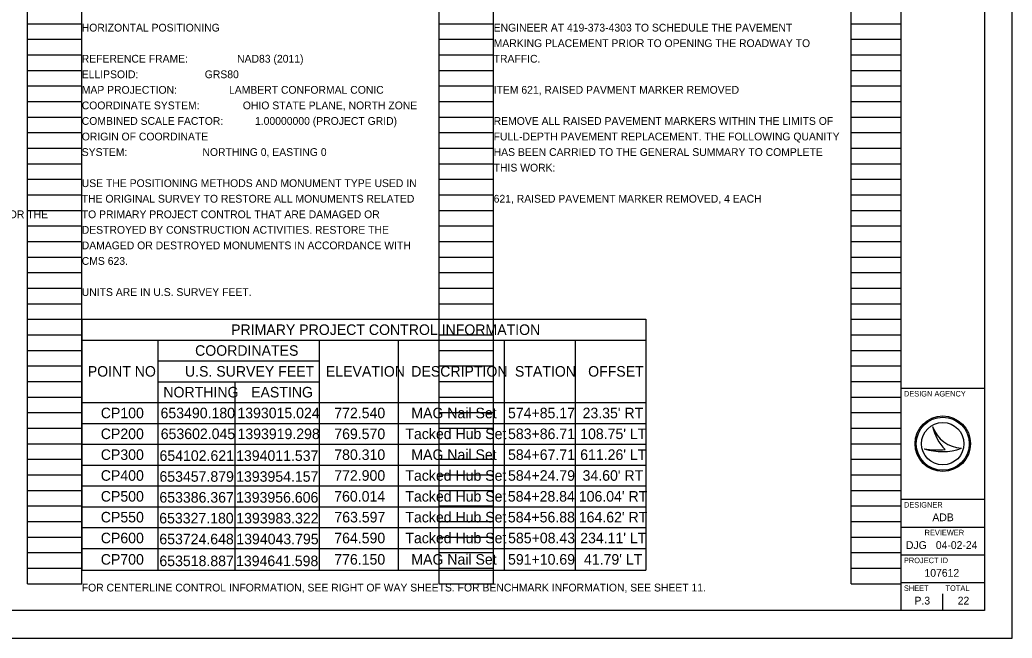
# Model space of a CAD drawing. Extents: x 0 to 34, y 0 to 22.
# Drawn here: x 16.13 to 34, y 0 to 11.13 of the extents above; entities that cross this region are included whole.
import ezdxf

# ---------------------------------------------------------------- set-up
doc = ezdxf.new("R2010")
doc.units = 0
for name, color, linetype in [('SH_Border', 7, 'Continuous'), ('SH_Cut_Line', 7, 'Continuous'), ('SH_Data', 7, 'Continuous'), ('SH_Text', 7, 'Continuous')]:
    doc.layers.add(name, color=color, linetype=linetype)

msp = doc.modelspace()

# ---------------------------------------------------------------- linework, layer by layer
at = {"layer": 'SH_Border'}
for p, q in [((32, 0.5), (32, 21.5)), ((32, 4.5), (33.5, 4.5)), ((32, 2.5), (33.5, 2.5)), ((32, 2), (33.5, 2)), ((32, 1.5), (33.5, 1.5)), ((32, 1), (33.5, 1))]:
    msp.add_line(p, q, dxfattribs=at)
msp.add_lwpolyline([(1.5, 21.5), (33.5, 21.5), (33.5, 0.5), (1.5, 0.5)], close=True, dxfattribs=at)
at = {"layer": 'SH_Cut_Line'}
msp.add_lwpolyline([(0, 0), (34, 0), (34, 22), (0, 22)], close=True, dxfattribs=at)
at = {"layer": 'SH_Data'}
for p, q in [((16.26, 0.98), (16.26, 21.14)), ((17.24, 0.98), (17.24, 21.14)), ((23.68, 0.98), (23.68, 21.14)), ((24.66, 0.98), (24.66, 21.14)), ((31.1, 0.98), (31.1, 21.14)), ((32, 0.98), (32, 21.14)), ((16.26, 11.06), (17.24, 11.06)), ((23.68, 11.06), (24.66, 11.06)), ((31.1, 11.06), (32, 11.06)), ((16.26, 10.78), (17.24, 10.78)), ((23.68, 10.78), (24.66, 10.78)), ((31.1, 10.78), (32, 10.78)), ((16.26, 10.5), (17.24, 10.5)), ((23.68, 10.5), (24.66, 10.5)), ((31.1, 10.5), (32, 10.5)), ((16.26, 10.22), (17.24, 10.22)), ((23.68, 10.22), (24.66, 10.22)), ((31.1, 10.22), (32, 10.22)), ((16.26, 9.94), (17.24, 9.94)), ((23.68, 9.94), (24.66, 9.94)), ((31.1, 9.94), (32, 9.94)), ((16.26, 9.66), (17.24, 9.66)), ((23.68, 9.66), (24.66, 9.66)), ((31.1, 9.66), (32, 9.66)), ((16.26, 9.38), (17.24, 9.38)), ((23.68, 9.38), (24.66, 9.38)), ((31.1, 9.38), (32, 9.38)), ((16.26, 9.1), (17.24, 9.1)), ((23.68, 9.1), (24.66, 9.1)), ((31.1, 9.1), (32, 9.1)), ((16.26, 8.82), (17.24, 8.82)), ((23.68, 8.82), (24.66, 8.82)), ((31.1, 8.82), (32, 8.82)), ((16.26, 8.54), (17.24, 8.54)), ((23.68, 8.54), (24.66, 8.54)), ((31.1, 8.54), (32, 8.54)), ((16.26, 8.26), (17.24, 8.26)), ((23.68, 8.26), (24.66, 8.26)), ((31.1, 8.26), (32, 8.26)), ((16.26, 7.98), (17.24, 7.98)), ((23.68, 7.98), (24.66, 7.98)), ((31.1, 7.98), (32, 7.98)), ((16.26, 7.7), (17.24, 7.7)), ((23.68, 7.7), (24.66, 7.7)), ((31.1, 7.7), (32, 7.7)), ((16.26, 7.42), (17.24, 7.42)), ((23.68, 7.42), (24.66, 7.42)), ((31.1, 7.42), (32, 7.42)), ((16.26, 7.14), (17.24, 7.14)), ((23.68, 7.14), (24.66, 7.14)), ((31.1, 7.14), (32, 7.14)), ((16.26, 6.86), (17.24, 6.86)), ((23.68, 6.86), (24.66, 6.86)), ((31.1, 6.86), (32, 6.86)), ((16.26, 6.58), (17.24, 6.58)), ((23.68, 6.58), (24.66, 6.58)), ((31.1, 6.58), (32, 6.58)), ((16.26, 6.3), (17.24, 6.3)), ((23.68, 6.3), (24.66, 6.3)), ((31.1, 6.3), (32, 6.3)), ((16.26, 6.02), (17.24, 6.02)), ((23.68, 6.02), (24.66, 6.02)), ((31.1, 6.02), (32, 6.02)), ((16.26, 5.74), (17.24, 5.74)), ((23.68, 5.74), (24.66, 5.74)), ((31.1, 5.74), (32, 5.74)), ((16.26, 5.46), (17.24, 5.46)), ((23.68, 5.46), (24.66, 5.46)), ((31.1, 5.46), (32, 5.46)), ((16.26, 5.18), (17.24, 5.18)), ((23.68, 5.18), (24.66, 5.18)), ((31.1, 5.18), (32, 5.18)), ((16.26, 4.9), (17.24, 4.9)), ((23.68, 4.9), (24.66, 4.9)), ((31.1, 4.9), (32, 4.9)), ((16.26, 4.62), (17.24, 4.62)), ((23.68, 4.62), (24.66, 4.62)), ((31.1, 4.62), (32, 4.62)), ((16.26, 4.34), (17.24, 4.34)), ((23.68, 4.34), (24.66, 4.34)), ((31.1, 4.34), (32, 4.34)), ((16.26, 4.06), (17.24, 4.06)), ((23.68, 4.06), (24.66, 4.06)), ((31.1, 4.06), (32, 4.06)), ((16.26, 3.78), (17.24, 3.78)), ((23.68, 3.78), (24.66, 3.78)), ((31.1, 3.78), (32, 3.78)), ((32.567, 3.81), (32.567, 3.81)), ((16.26, 3.5), (17.24, 3.5)), ((23.68, 3.5), (24.66, 3.5)), ((31.1, 3.5), (32, 3.5)), ((32.417, 3.41), (32.417, 3.41)), ((32.75, 3.5), (32.75, 3.5)), ((33.087, 3.419), (33.087, 3.419)), ((16.26, 3.22), (17.24, 3.22)), ((23.68, 3.22), (24.66, 3.22)), ((31.1, 3.22), (32, 3.22)), ((16.26, 2.94), (17.24, 2.94)), ((23.68, 2.94), (24.66, 2.94)), ((31.1, 2.94), (32, 2.94)), ((16.26, 2.66), (17.24, 2.66)), ((23.68, 2.66), (24.66, 2.66)), ((31.1, 2.66), (32, 2.66)), ((16.26, 2.38), (17.24, 2.38)), ((23.68, 2.38), (24.66, 2.38)), ((31.1, 2.38), (32, 2.38)), ((16.26, 2.1), (17.24, 2.1)), ((23.68, 2.1), (24.66, 2.1)), ((31.1, 2.1), (32, 2.1)), ((16.26, 1.82), (17.24, 1.82)), ((23.68, 1.82), (24.66, 1.82)), ((31.1, 1.82), (32, 1.82)), ((16.26, 1.54), (17.24, 1.54)), ((23.68, 1.54), (24.66, 1.54)), ((31.1, 1.54), (32, 1.54)), ((16.26, 1.26), (17.24, 1.26)), ((23.68, 1.26), (24.66, 1.26)), ((31.1, 1.26), (32, 1.26)), ((16.26, 0.98), (17.24, 0.98)), ((23.68, 0.98), (24.66, 0.98)), ((31.1, 0.98), (32, 0.98)), ((32.75, 0.5), (32.75, 0.8)), ((32.375, 0.675), (32.375, 0.675))]:
    msp.add_line(p, q, dxfattribs=at)
for radius in [0.5, 0.477, 0.477, 0.382]:
    msp.add_circle((32.75, 3.5), radius, dxfattribs=at)
for centre, radius, start, end in [((33.116, 3.998), 0.58, 198.9257, 198.9319), ((33.347, 3.97), 0.796, 191.6379, 191.6421), ((33.116, 3.998), 0.58, 198.9319, 267.1657), ((33.347, 3.97), 0.796, 191.6421, 226.0947), ((32.739, 4.37), 1.013, 251.4576, 290.0832), ((32.648, 4.654), 1.266, 259.4964, 259.4995), ((32.739, 4.37), 1.013, 251.4527, 251.4576), ((32.648, 4.654), 1.266, 259.4995, 276.6672)]:
    msp.add_arc(centre, radius, start, end, dxfattribs=at)
at = {"layer": 'SH_Text'}
for p, q in [((17.24, 5.74), (27.402, 5.74)), ((17.24, 5.74), (17.24, 1.221)), ((27.402, 5.74), (27.402, 1.221)), ((17.24, 5.365), (27.402, 5.365)), ((18.609, 5.365), (18.609, 1.221)), ((21.515, 5.365), (21.515, 1.221)), ((22.94, 5.365), (22.94, 1.221)), ((24.852, 5.365), (24.852, 1.221)), ((26.127, 5.365), (26.127, 1.221)), ((18.609, 4.99), (21.515, 4.99)), ((18.609, 4.615), (21.515, 4.615)), ((19.996, 4.615), (19.996, 1.221)), ((17.24, 4.24), (27.402, 4.24)), ((17.24, 3.865), (27.402, 3.865)), ((17.24, 3.49), (27.402, 3.49)), ((17.24, 3.115), (27.402, 3.115)), ((17.24, 2.74), (27.402, 2.74)), ((17.24, 2.365), (27.402, 2.365)), ((17.24, 1.99), (27.402, 1.99)), ((17.24, 1.615), (27.402, 1.615)), ((17.24, 1.221), (27.402, 1.221))]:
    msp.add_line(p, q, dxfattribs=at)

# ---------------------------------------------------------------- texts
at = {"layer": 'SH_Data'}
for s, height, p in [('DESIGN AGENCY', 0.1, (32.05, 4.35)), ('DESIGNER', 0.1, (32.05, 2.35)), ('ADB', 0.14, (32.563, 2.105)), ('REVIEWER', 0.1, (32.422, 1.85)), ('DJG', 0.14, (32.087, 1.605)), ('04-02-24', 0.14, (32.625, 1.605)), ('PROJECT ID', 0.1, (32.05, 1.35)), ('107612', 0.14, (32.421, 1.105)), ('SHEET', 0.1, (32.05, 0.85)), ('TOTAL', 0.1, (32.8, 0.85)), ('P.3', 0.14, (32.241, 0.605)), ('22', 0.14, (33.019, 0.605))]:
    msp.add_text(s, height=height, dxfattribs=at).set_placement(p)
at = {"layer": 'SH_Text'}
for s, height, p in [('HORIZONTAL POSITIONING', 0.14, (17.24, 10.92)), ('ENGINEER AT 419-373-4303 TO SCHEDULE THE PAVEMENT', 0.14, (24.66, 10.92)), ('MARKING PLACEMENT PRIOR TO OPENING THE ROADWAY TO', 0.14, (24.66, 10.64)), ('REFERENCE FRAME:                 NAD83 (2011)', 0.14, (17.24, 10.36)), ('TRAFFIC.', 0.14, (24.66, 10.36)), ('ELLIPSOID:                       GRS80', 0.14, (17.24, 10.08)), ('MAP PROJECTION:                  LAMBERT CONFORMAL CONIC', 0.14, (17.24, 9.8)), ('ITEM 621, RAISED PAVMENT MARKER REMOVED', 0.14, (24.66, 9.8)), ('COORDINATE SYSTEM:               OHIO STATE PLANE, NORTH ZONE', 0.14, (17.24, 9.52)), ('COMBINED SCALE FACTOR:           1.00000000 (PROJECT GRID)', 0.14, (17.24, 9.24)), ('REMOVE ALL RAISED PAVEMENT MARKERS WITHIN THE LIMITS OF', 0.14, (24.66, 9.24)), ('ORIGIN OF COORDINATE', 0.14, (17.24, 8.96)), ('FULL-DEPTH PAVEMENT REPLACEMENT. THE FOLLOWING QUANITY', 0.14, (24.66, 8.96)), ('SYSTEM:                          NORTHING 0, EASTING 0', 0.14, (17.24, 8.68)), ('HAS BEEN CARRIED TO THE GENERAL SUMMARY TO COMPLETE', 0.14, (24.66, 8.68)), ('THIS WORK:', 0.14, (24.66, 8.4)), ('USE THE POSITIONING METHODS AND MONUMENT TYPE USED IN', 0.14, (17.24, 8.12)), ('THE ORIGINAL SURVEY TO RESTORE ALL MONUMENTS RELATED', 0.14, (17.24, 7.84)), ('621, RAISED PAVEMENT MARKER REMOVED, 4 EACH', 0.14, (24.66, 7.84)), ('REFER TO THE SUBSUMMARY FOR THE ESTIMATED QUANTITIES FOR THE', 0.14, (9.82, 7.56)), ('TO PRIMARY PROJECT CONTROL THAT ARE DAMAGED OR', 0.14, (17.24, 7.56)), ('DESTROYED BY CONSTRUCTION ACTIVITIES. RESTORE THE', 0.14, (17.24, 7.28)), ('DAMAGED OR DESTROYED MONUMENTS IN ACCORDANCE WITH', 0.14, (17.24, 7)), ('CMS 623.', 0.14, (17.24, 6.72)), ('UNITS ARE IN U.S. SURVEY FEET.', 0.14, (17.24, 6.16)), ('PRIMARY PROJECT CONTROL INFORMATION', 0.18975, (19.931, 5.458)), ('COORDINATES', 0.18975, (19.282, 5.083)), ('POINT NO.', 0.1898, (17.349, 4.708)), ('U.S. SURVEY FEET', 0.18975, (19.1, 4.708)), ('ELEVATION', 0.1898, (21.638, 4.708)), ('DESCRIPTION', 0.18975, (23.176, 4.708)), ('STATION', 0.1898, (25.043, 4.708)), ('OFFSET', 0.1898, (26.362, 4.708)), ('NORTHING', 0.1898, (18.71, 4.333)), ('EASTING', 0.1898, (20.291, 4.333)), ('CP100', 0.1898, (17.583, 3.958)), ('653490.180', 0.1898, (18.66, 3.958)), ('1393015.024', 0.18975, (20.044, 3.958)), ('772.540', 0.1898, (21.789, 3.958)), ('MAG Nail Set', 0.18975, (23.177, 3.958)), ('574+85.17', 0.1898, (24.918, 3.958)), ("23.35' RT", 0.1898, (26.262, 3.958)), ('CP200', 0.1898, (17.583, 3.583)), ('653602.045', 0.1898, (18.663, 3.583)), ('1393919.298', 0.18975, (20.046, 3.583)), ('769.570', 0.1898, (21.789, 3.583)), ('Tacked Hub Set', 0.18975, (23.07, 3.583)), ('583+86.71', 0.1898, (24.919, 3.583)), ("108.75' LT", 0.1898, (26.219, 3.583)), ('CP300', 0.1898, (17.583, 3.208)), ('780.310', 0.1898, (21.789, 3.208)), ('MAG Nail Set', 0.18975, (23.177, 3.208)), ('584+67.71', 0.1898, (24.919, 3.208)), ("611.26' LT", 0.1898, (26.219, 3.208)), ('654102.621', 0.1898, (18.641, 3.19)), ('1394011.537', 0.18975, (20.021, 3.19)), ('CP400', 0.1898, (17.583, 2.833)), ('653457.879', 0.1898, (18.64, 2.815)), ('1393954.157', 0.18975, (20.021, 2.815)), ('772.900', 0.1898, (21.789, 2.833)), ('Tacked Hub Set', 0.18975, (23.07, 2.833)), ('584+24.79', 0.1898, (24.919, 2.833)), ("34.60' RT", 0.1898, (26.262, 2.833)), ('CP500', 0.1898, (17.583, 2.458)), ('653386.367', 0.1898, (18.639, 2.44)), ('1393956.606', 0.18975, (20.02, 2.44)), ('760.014', 0.1898, (21.788, 2.458)), ('Tacked Hub Set', 0.18975, (23.07, 2.458)), ('584+28.84', 0.1898, (24.916, 2.458)), ("106.04' RT", 0.1898, (26.194, 2.458)), ('CP550', 0.1898, (17.583, 2.083)), ('653327.180', 0.1898, (18.636, 2.065)), ('1393983.322', 0.18975, (20.024, 2.065)), ('763.597', 0.1898, (21.791, 2.083)), ('Tacked Hub Set', 0.18975, (23.07, 2.083)), ('584+56.88', 0.1898, (24.917, 2.083)), ("164.62' RT", 0.1898, (26.194, 2.083)), ('CP600', 0.1898, (17.583, 1.708)), ('653724.648', 0.1898, (18.638, 1.69)), ('1394043.795', 0.18975, (20.025, 1.69)), ('764.590', 0.1898, (21.789, 1.708)), ('Tacked Hub Set', 0.18975, (23.07, 1.708)), ('585+08.43', 0.1898, (24.92, 1.708)), ("234.11' LT", 0.1898, (26.219, 1.708)), ('CP700', 0.1898, (17.583, 1.323)), ('653518.887', 0.1898, (18.639, 1.296)), ('1394641.598', 0.18975, (20.02, 1.296)), ('776.150', 0.1898, (21.789, 1.323)), ('MAG Nail Set', 0.18975, (23.177, 1.323)), ('591+10.69', 0.1898, (24.919, 1.323)), ("41.79' LT", 0.1898, (26.287, 1.323)), ('FOR CENTERLINE CONTROL INFORMATION, SEE RIGHT OF WAY SHEETS. FOR BENCHMARK INFORMATION, SEE SHEET 11.', 0.14, (17.24, 0.84))]:
    msp.add_text(s, height=height, dxfattribs=at).set_placement(p)

doc.saveas('drawing.dxf')
